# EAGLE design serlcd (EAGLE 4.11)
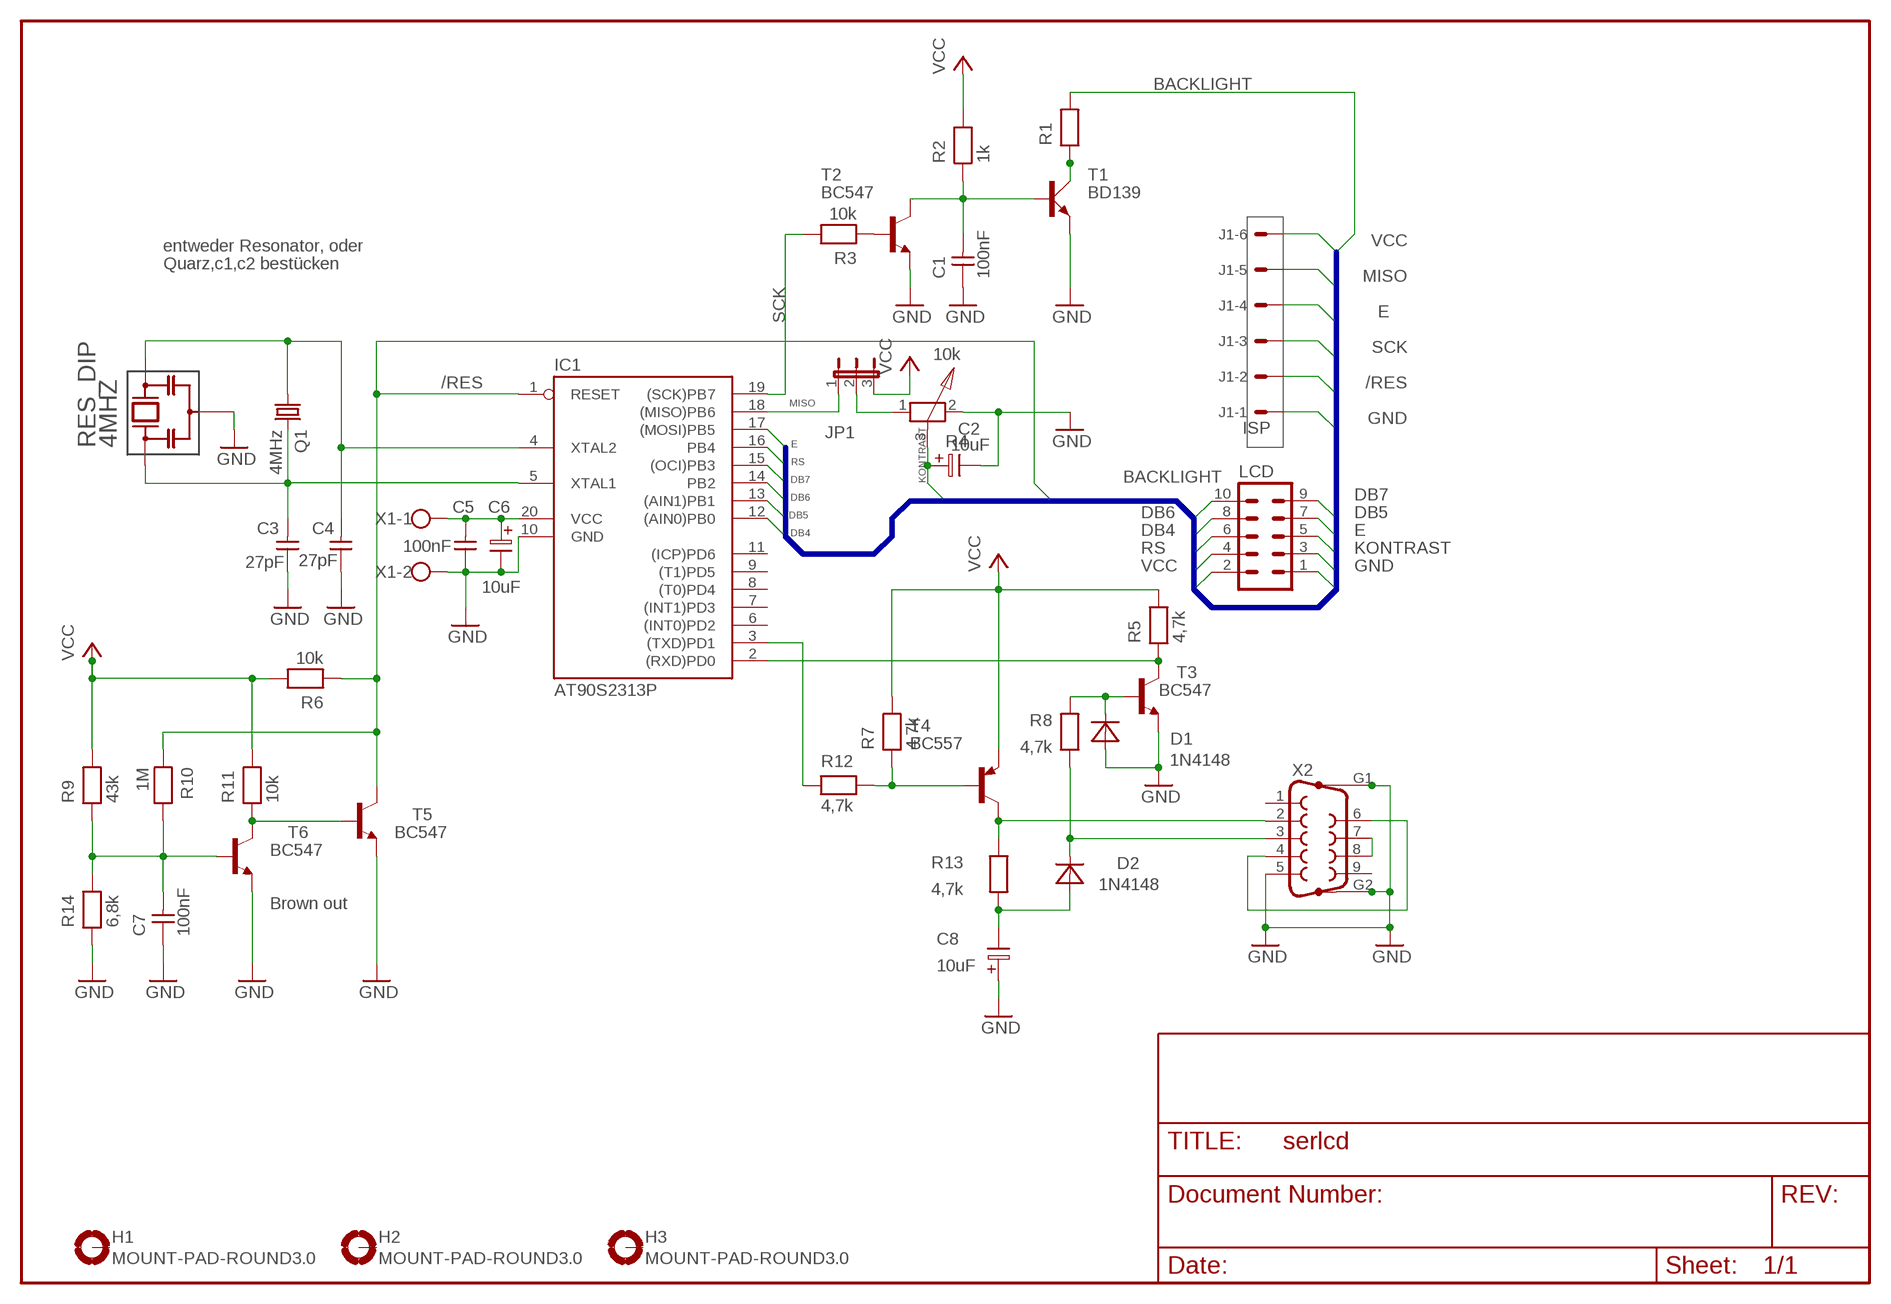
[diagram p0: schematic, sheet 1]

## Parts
4MHZ  RES_DIP  [RESONDIP]
C1  100nF  CAPNP-5  [C-5]
C2  10uF  ELC-2,5  [ES-2,5]
C3  27pF  CAPNP-2,5  [C-2,5]
C4  27pF  CAPNP-2,5  [C-2,5]
C5  100nF  CAPNP-5  [C-5]
C6  10uF  ELC-2,5  [ES-2,5]
C7  100nF  CAPNP-5  [C-5]
C8  10uF  ELC-2,5  [ES-2,5]
D1  1N4148  DIODE-7,5  [D-7,5]
D2  1N4148  DIODE-7,5  [D-7,5]
H1  MOUNT-PAD-ROUND3.0  [3,0-PAD]
H2  MOUNT-PAD-ROUND3.0  [3,0-PAD]
H3  MOUNT-PAD-ROUND3.0  [3,0-PAD]
IC1  AT90S2313P  [DIL20]
J1  ISP  22-27-2061-06  [6410-06]
JP1  JP2E  [JP2]
LCD  ML10  [ML10]
Q1  4MHz  CRYTALHC49S  [HC49/S]
R1  RESEU-12,5  [R-12,5]
R2  1k  RESEU-7,5  [R-7,5]
R3  10k  RESEU-7,5  [R-7,5]
R4  10k  POT-L  [PT-10]
R5  4,7k  RESEU-7,5  [R-7,5]
R6  10k  RESEU-7,5  [R-7,5]
R7  4,7k  RESEU-7,5  [R-7,5]
R8  4,7k  RESEU-7,5  [R-7,5]
R9  43k  RESEU-7,5  [R-7,5]
R10  1M  RESEU-7,5  [R-7,5]
R11  10k  RESEU-7,5  [R-7,5]
R12  4,7k  RESEU-7,5  [R-7,5]
R13  4,7k  RESEU-7,5  [R-7,5]
R14  6,8k  RESEU-7,5  [R-7,5]
T1  BD139  [TO126AV]
T2  BC547  [TO92]
T3  BC547  [TO92]
T4  BC557  [TO92]
T5  BC547  [TO92]
T6  BC547  [TO92]
X1  W237-102  [W237-102]
X2  F09HP  [F09HP]

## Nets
/RES: IC1.1(RESET) J1.2 R6.1 R10.1 T5.3(C)
BACKLIGHT: LCD.10 R1.2
DB4: IC1.12((AIN0)PB0) LCD.6
DB5: IC1.13((AIN1)PB1) LCD.7
DB6: IC1.14(PB2) LCD.8
DB7: IC1.15((OCI)PB3) LCD.9
E: IC1.17((MOSI)PB5) J1.4 LCD.5
GND: 4MHZ.GND C1.1 C2.2 C3.1 C4.1 C5.1 C6.2 C7.1 C8.1 D1.1(A) IC1.10(GND) J1.1 LCD.1 R4.2 R14.1 T1.E T2.1(E) T3.1(E) T5.1(E) T6.1(E) X1.2 X2.5 X2.G1 X2.G2
KONTRAST: C2.1 LCD.3 R4.3
MISO: IC1.18((MISO)PB6) J1.5 JP1.1
N$1: 4MHZ.IN C3.2 IC1.5(XTAL1) Q1.2
N$2: IC1.3((TXD)PD1) R12.1
N$3: 4MHZ.OUT C4.2 IC1.4(XTAL2) Q1.1
N$4: R7.1 R12.2 T4.2(B)
N$5: R13.2 T4.3(C) X2.2
N$6: D2.2(K) R8.1 X2.3
N$7: C8.2 D2.1(A) R13.1
N$8: D1.2(K) R8.2 T3.2(B)
N$9: IC1.2((RXD)PD0) R5.1 T3.3(C)
N$12: C7.2 R9.1 R10.2 R14.2 T6.2(B)
N$13: R11.1 T5.2(B) T6.3(C)
N$15: C1.2 R2.1 T1.B T2.3(C)
N$18: R3.1 T2.2(B)
N$20: R1.1 T1.C
N$21: JP1.2 R4.1
N$24: X2.7 X2.8
N$25: X2.4 X2.6
RS: IC1.16(PB4) LCD.4
SCK: IC1.19((SCK)PB7) J1.3 R3.2
VCC: C5.2 C6.1 IC1.20(VCC) J1.6 JP1.3 LCD.2 R2.2 R5.2 R6.2 R7.2 R9.2 R11.2 T4.1(E) X1.1
Unconnected: H1.B3,0(MOUNT) H2.B3,0(MOUNT) H3.B3,0(MOUNT) IC1.6((INT0)PD2) IC1.7((INT1)PD3) IC1.8((T0)PD4) IC1.9((T1)PD5) IC1.11((ICP)PD6) X2.1 X2.9

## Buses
DB[4..7],KONTRAST,BACKLIGHT,VCC,GND,E,RS,/RES,SCK,MISO

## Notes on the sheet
- entweder Resonator, oder
- Quarz,c1,c2 bestücken
- Brown out

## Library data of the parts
4MHZ = 0_jmw:RES_DIP
C1 C5 C7 = discrete:CAPNP-5
C2 C6 C8 = discrete:ELC-2,5
C3 C4 = discrete:CAPNP-2,5
D1 D2 = discrete:DIODE-7,5
H1-H3 = holes:MOUNT-PAD-ROUND: MOUNTING PAD, round
IC1 = atmel:AT90S2313: MICROCONTROLLER 2 Kbytes FLASH 128 bytes SRAM 128 bytes EEPROM UART
J1 = ep_molex_6410_7395-02:22-?-06: CONNECTOR wire to board 2.54 mm (.1 inch) pitch header
JP1 = jumper:JP2E: JUMPER
LCD = con-ml:ML10: HARTING
Q1 = crystal:CRYTAL: CRYSTAL
R1 = discrete:RESEU-12,5
R2 R3 R5-R14 = discrete:RESEU-7,5
R4 = discrete:POT-L
T1 = transistor-power:BD139: NPN TRANSISTOR
T2 T3 T5 T6 = transistor:BC547: NPN TRANSISTOR
T4 = transistor-pnp:BC557: PNP Transistor
X1 = con-wago-500:W237-102: WAGO SCREW CLAMP
X2 = con-subd:F09HP: SUB-D

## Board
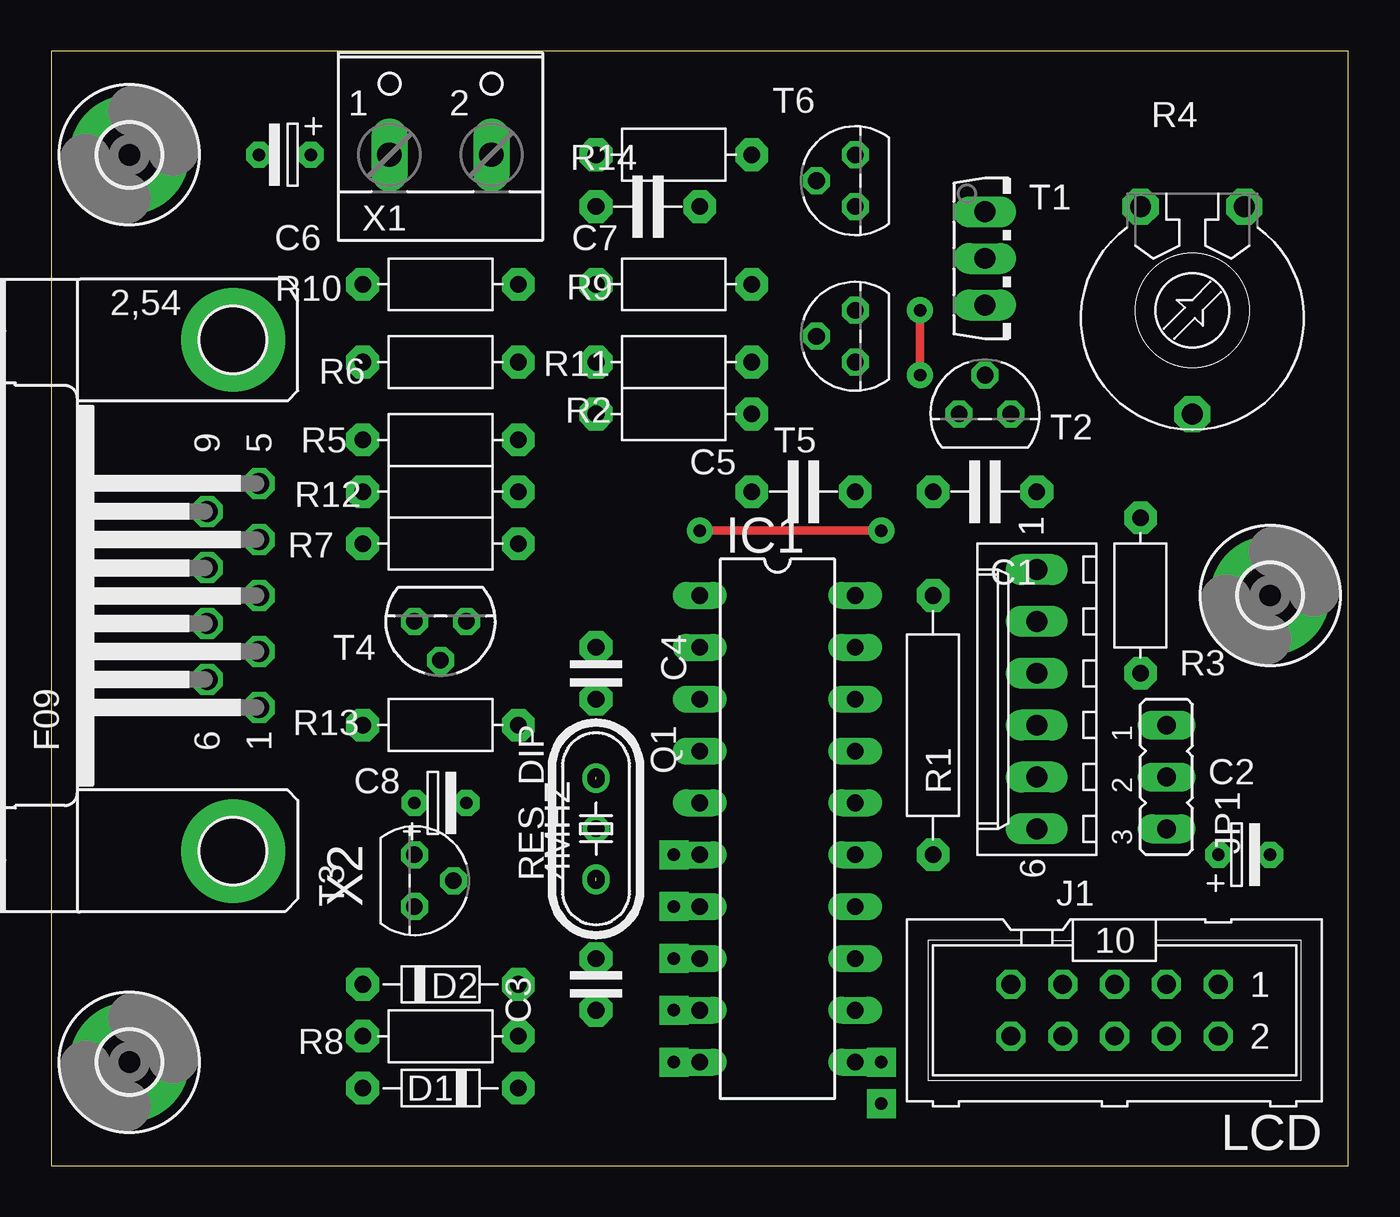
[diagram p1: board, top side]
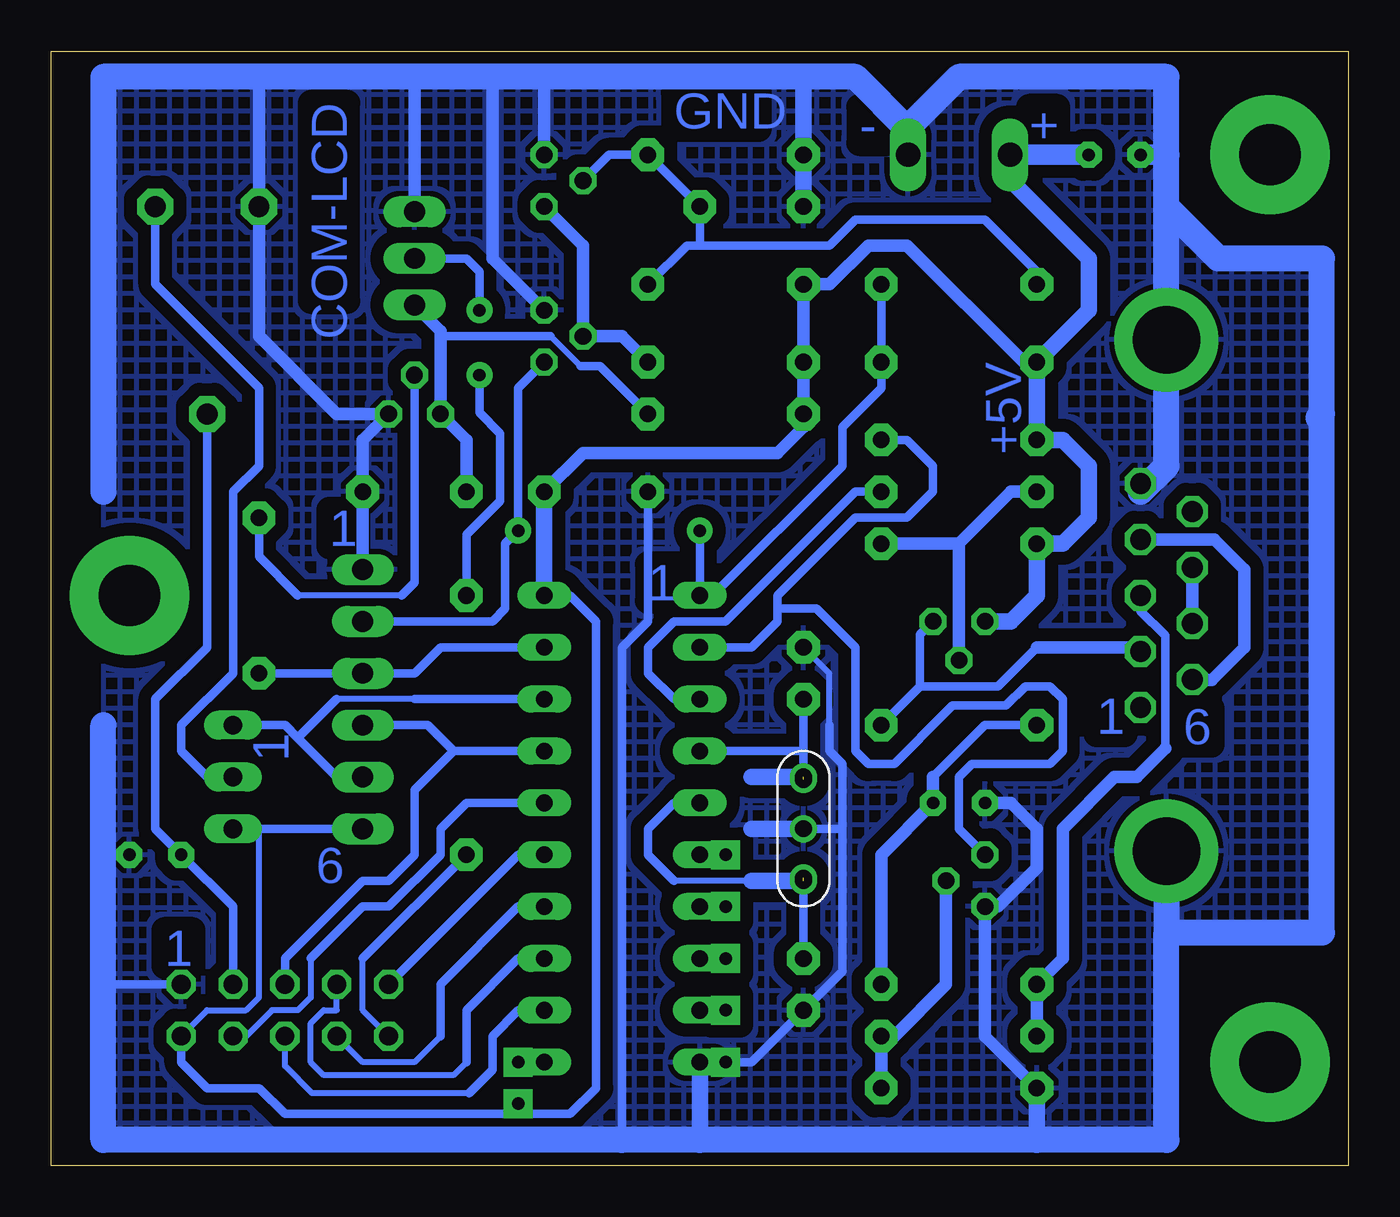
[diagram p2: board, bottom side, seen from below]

Size 63.55 x 54.6 mm. Coordinates in mm from the lower left corner, seen from the top.
Outline: 0,0 63.55,0 63.55,54.6 0,54.6 0,0
Copper layers (1*16): Top 0.035mm / dielectric 1.5mm / Bottom 0.035mm
Design rules "default": minimum track width 10mil, minimum drill 24mil, track to track 25mil, track to pad 25mil, pad to pad 25mil, via to via 25mil, smd to smd 8mil, copper to edge 40mil, drill to drill 8mil, minimum pad ring 10mil, minimum via ring 8mil, stop-mask expansion 4mil, vias tented up to drill 0mil, thermal gap 10mil

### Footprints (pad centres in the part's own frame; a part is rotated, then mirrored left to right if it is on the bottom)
RESONDIP = drill 0.813 round: GND 0,0; IN -2.54,0; OUT 2.54,0
C-5 = drill 0.813 pad 1.6 octagon: 1 -2.54,0; 2 2.54,0
ES-2,5 = drill 0.61 pad 1.27 octagon: 1 -1.27,0; 2 1.27,0
C-2,5 = drill 0.813 pad 1.6 octagon: 1 -1.27,0; 2 1.27,0
D-7,5 = drill 0.813 pad 1.6 octagon: 1 -3.81,0; 2 3.81,0
3,0-PAD = drill 3 pad 5.842 round: B3,0 0,0
DIL20 = drill 0.813 long: 1 -11.43,-3.81; 2 -8.89,-3.81; 3 -6.35,-3.81; 4 -3.81,-3.81; 5 -1.27,-3.81; 6 1.27,-3.81; 7 3.81,-3.81; 8 6.35,-3.81; 9 8.89,-3.81; 10 11.43,-3.81; 11 11.43,3.81; 12 8.89,3.81; 13 6.35,3.81; 14 3.81,3.81; 15 1.27,3.81; 16 -1.27,3.81; 17 -3.81,3.81; 18 -6.35,3.81; 19 -8.89,3.81; 20 -11.43,3.81
6410-06 = drill 1.016 long: 1 6.35,0; 2 3.81,0; 3 1.27,0; 4 -1.27,0; 5 -3.81,0; 6 -6.35,0
JP2 = drill 0.914 long: 1 -2.54,0; 2 0,0; 3 2.54,0
ML10 = drill 0.914 octagon: 1 -5.08,-1.27; 2 -5.08,1.27; 3 -2.54,-1.27; 4 -2.54,1.27; 5 0,-1.27; 6 0,1.27; 7 2.54,-1.27; 8 2.54,1.27; 9 5.08,-1.27; 10 5.08,1.27
HC49/S = drill 0.813 round: 1 -2.413,0; 2 2.413,0
R-12,5 = drill 0.813 pad 1.6 octagon: 1 -6.35,0; 2 6.35,0
R-7,5 = drill 0.813 pad 1.6 octagon: 1 -3.81,0; 2 3.81,0
PT-10 = drill 1.016 pad 1.778 octagon: 1 -2.54,-5.08; 2 2.54,-5.08; 3 0,5.08
TO126AV = drill 1.016 long: B 2.286,-1.27; C 0,-1.27; E -2.286,-1.27
TO92 = drill 0.813 octagon: 1 1.27,0; 2 0,1.905; 3 -1.27,0
HEBW21 = drill 2.184 pad 2.54 long: MASSE 0,6.5; STIFT 0,0.3; ÖFFNER -5.3,3.4
W237-102 = drill 1.194 long: 1 -2.5,-1.27; 2 2.5,-1.27
F09HP = drill 1.016 octagon: 1 -5.486,-1.27; 2 -2.743,-1.27; 3 0,-1.27; 4 2.743,-1.27; 5 5.486,-1.27; 6 -4.115,1.27; 7 -1.372,1.27; 8 1.372,1.27; 9 4.115,1.27 | drill 3.302 pad 5.08 round: G1 -12.522,0; G2 12.522,0

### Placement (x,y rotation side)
4MHZ  26.7,16.5 90 top
C1  45.75,33.02 180 top
C2  58.45,15.24 0 top
C3  26.7,8.88 90 top
C4  26.7,24.12 270 top
C5  36.86,33.02 0 top
C6  11.46,49.52 180 top
C7  29.24,46.98 0 top
C8  19.08,17.78 0 top
D1  19.08,3.8 0 top
D2  19.08,8.88 180 top
H1  3.84,49.52 0 top
H2  59.72,27.94 0 top
H3  3.84,5.08 0 top
IC1  35.59,16.5 270 top
J1  48.29,22.86 90 top
JP1  54.64,19.05 270 top
LCD  52.1,7.61 180 top
Q1  26.7,16.5 270 top
R1  43.21,21.59 270 top
R2  30.51,36.83 180 top
R3  53.37,27.94 270 top
R4  55.91,41.91 180 top
R5  19.08,35.55 180 top
R6  19.08,39.37 180 top
R7  19.08,30.48 180 top
R8  19.08,6.34 0 top
R9  30.51,43.17 180 top
R10  19.08,43.17 180 top
R11  30.51,39.37 180 top
R12  19.08,33.02 180 top
R13  19.08,21.59 0 top
R14  30.51,49.52 0 top
T1  47.02,44.45 270 top
T2  45.75,36.83 0 top
T3  17.81,13.96 270 top
T4  19.08,26.66 180 top
T5  39.4,40.63 90 top
T6  39.4,48.26 90 top
U$1  POWERBUCHSE21  [HEBW21]  not placed on the board
X1  19.08,50.8 0 top
X2  8.92,27.94 90 top

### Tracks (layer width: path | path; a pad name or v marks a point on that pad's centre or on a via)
/RES  (via drill 0.61 pad 1.27)
  Top 0.406: v31.78,31.11 v40.67,31.11
  Bottom 0.406: R10.1 R6.1 22.89,38.09 24.79,36.19 24.79,34.29 31.14,27.94 IC1.1 v31.78,31.11 | T5.3 40.67,38.09 v40.67,31.11 41.3,30.48 41.3,27.3 41.94,26.66 J1.2
BACKLIGHT
  Bottom 0.305: LCD.10 48.29,7.61 48.29,10.16
  Bottom 0.406: 48.29,10.16 R1.2
DB4
  Bottom 0.305: LCD.6 52.1,4.88 50.76,3.55 43.08,3.55
  Bottom 0.406: IC1.12 40.67,7.61 41.94,6.34 41.94,4.69 43.08,3.55
DB5
  Bottom 0.305: LCD.7 49.56,7.61 50.19,7.61 50.83,6.98 50.83,5.08 50.19,4.44 43.84,4.44 43.21,5.08
  Bottom 0.406: IC1.13 40.67,10.16 43.21,7.61 43.21,5.08
DB6
  Bottom 0.305: 44.48,6.34 45.75,5.08 48.29,5.08 LCD.8
  Bottom 0.406: IC1.14 40.67,12.7 44.48,8.88 44.48,6.34
DB7
  Bottom 0.406: IC1.15 40.67,15.24 LCD.9
E
  Bottom 0.406: 43.84,20.32 45.75,18.41 45.75,15.24 47.02,13.96 48.29,13.96 52.1,10.16 LCD.5 | IC1.17 43.84,20.32 | J1.4 45.11,21.59 43.84,20.32
GND  (via drill 0.61 pad 1.42)
  Bottom 0.305: C4.1 25.43,24.12 25.43,21.59
  Bottom 0.406: IC1.10 v30.51,5.08 29.24,5.08 C3.1 24.79,9.52 24.79,16.5 | 60.99,8.88 LCD.1 | 24.79,16.5 24.79,19.68 25.43,20.32 25.43,21.59 | 24.79,16.5 4MHZ.GND | C5.1 34.32,26.66 35.59,25.39 35.59,1.26
  Bottom 0.61: D1.1 17.81,6.34 T3.1 17.17,12.7 15.27,14.6 15.27,16.5 16.54,17.78 C8.1 | 39.4,53.34 T6.1 | 45.75,53.34 T1.E | T5.1 41.94,44.45 41.94,53.34 | J1.1 C1.1 48.29,35.55 T2.1 49.56,36.83 53.37,40.63 R4.2 53.37,53.34
  Bottom 0.813: C7.1 R14.1 26.7,53.34 | 15.27,1.26 D1.1 | 31.78,1.26 IC1.10 | 4MHZ.GND 29.24,16.5
  Bottom 1.016: 8.92,49.52 C6.2
  Bottom 1.27: X1.2 21.58,50.76 24.16,53.34 26.7,53.34 39.4,53.34 41.94,53.34 45.75,53.34 53.37,53.34 60.99,53.34 60.99,33.02 | 1.3,36.83 1.47,36.65 | 1.3,36.83 1.3,44.45 6.38,44.45 8.92,46.98 | 8.92,46.98 8.92,49.52 8.92,53.34 19.08,53.34 21.62,50.8 21.62,49.52 | 8.92,11.43 1.3,11.43 1.3,36.83 | 8.92,11.43 8.92,1.26 15.27,1.26 31.78,1.26 35.59,1.26 60.99,1.26 60.99,8.88 60.99,21.59 | 10.19,33.02 8.92,34.29 8.92,46.98 | 8.92,15.24 8.92,11.43
  pour Bottom (isolate 0.254, hatched): 8.92,53.34 19.08,53.34 21.62,50.8 24.16,53.34 60.99,53.34 60.99,1.26 8.92,1.26 8.92,11.43 1.3,11.43 1.3,44.45 6.38,44.45 8.92,46.98
KONTRAST
  Bottom 0.406: LCD.3 54.64,12.7 C2.1 58.45,16.5 58.45,22.86 55.91,25.39 R4.3
MISO
  Bottom 0.305: 45.75,22.86 49.56,22.86
  Bottom 0.406: J1.5 49.56,19.05 51.46,20.95 | 51.46,20.95 52.1,21.59 JP1.1 | 49.56,22.86 51.46,20.95 | IC1.18 45.75,22.86
N$1  (1 unrouted)
  Bottom 0.305: 29.24,13.96 33.05,13.96
  Bottom 0.406: C3.2 4MHZ.IN | 33.05,13.96 34.32,15.24 34.32,16.5 33.05,17.78 IC1.5
  Bottom 0.813: 4MHZ.IN 29.24,13.96
N$2
  Bottom 0.406: R12.1 24.16,33.02 30.51,26.66 33.05,26.66 34.32,25.39 34.32,24.12 33.05,22.86 IC1.3
N$3  (1 unrouted)
  Bottom 0.406: 4MHZ.OUT 26.7,20.32 | 26.7,20.32 C4.2 | 26.7,20.32 IC1.4
  Bottom 0.813: 4MHZ.OUT 29.24,19.05
N$4
  Bottom 0.61: T4.2 19.08,30.48 | 19.08,30.48 R7.1 | R12.2 16.54,33.02 19.08,30.48
N$5
  Bottom 0.406: 20.98,23.49 R13.2 | T4.3 20.98,26.03 20.98,23.49 | 20.98,23.49 17.17,23.49 15.27,25.39 | X2.2 10.19,25.39
  Bottom 0.61: 10.19,25.39 15.27,25.39
N$6
  Bottom 0.406: X2.3 10.19,27.17 8.98,25.97 8.98,20.44
  Bottom 0.61: R8.1 D2.2 14,10.16 14,16.5 11.46,19.05 10.38,19.05 8.98,20.44
N$7
  Bottom 0.406: R13.1 17.81,21.59 20.35,19.05
  Bottom 0.61: 20.35,19.05 C8.2 22.89,15.24 D2.1
N$8
  Bottom 0.61: D1.2 R8.2 22.25,6.34 19.71,8.88 T3.2
N$9
  Bottom 0.406: T3.3 19.08,16.5 19.08,19.05 18.44,19.68 14.63,19.68 14,20.32 14,22.86 14.63,23.49 15.84,23.49 16.79,22.54 19.39,22.54 19.71,22.22 22.25,19.68 23.52,19.68 24.16,20.32 24.16,25.39 26.06,27.3 27.97,27.3 | R5.1 21.62,35.55 20.35,34.29 20.35,33.02 21.62,31.75 24.16,31.75 27.97,27.94 27.97,27.3 | 27.97,27.3 27.97,26.66 29.24,25.39 IC1.2
N$12
  Bottom 0.406: T6.2 36.22,49.52 R14.2 C7.2 31.78,45.08 | 31.78,45.08 25.43,45.08 24.16,46.35 17.81,46.35 15.27,43.81 R10.2 | 31.78,45.08 32.41,45.08 R9.1
N$13
  Bottom 0.61: R11.1 35.59,40.63 T5.2 37.49,45.08 T6.3
N$14  (via drill 0.61 pad 1.42)
  other vias: 30.51,7.61
N$15
  Bottom 0.305: 37.62,39.17 39.08,40.63
  Bottom 0.406: 39.08,40.63 44.48,40.63 | 37.62,39.17 36.66,39.17 R2.1
  Bottom 0.61: C1.2 43.21,35.55 T2.3 44.48,40.63 44.48,40.89 T1.B
N$16  (via drill 0.61 pad 1.42)
  other vias: 30.51,10.16
N$17  (via drill 0.61 pad 1.42)
  other vias: 30.51,12.7
N$18
  Bottom 0.305: 46.38,27.94 51.46,27.94
  Bottom 0.406: T2.2 45.75,28.57 46.38,27.94 | 51.46,27.94 53.37,29.84 R3.1
N$19  (via drill 0.61 pad 1.42)
  other vias: 30.51,15.24
N$20  (via drill 0.61 pad 1.27)
  Top 0.406: v42.57,38.73 v42.57,41.91
  Bottom 0.406: T1.C 43.21,44.45 42.57,43.81 v42.57,41.91 | R1.1 43.21,30.92 41.55,32.57 41.55,35.87 42.57,36.89 v42.57,38.73
N$21
  Bottom 0.406: JP1.2 55.91,19.05 57.18,20.32 57.18,21.59 54.64,24.12 54.64,33.02 53.37,34.29 53.37,38.09 58.45,43.17 R4.1
N$22  (via drill 0.61 pad 1.42)
  other vias: 40.67,3.04
N$23  (via drill 0.61 pad 1.42)
  other vias: 40.67,5.08
N$24
  Bottom 0.61: X2.7 X2.8
N$25
  Bottom 0.406: 7.65,23.81 X2.6
  Bottom 0.61: X2.4 6.58,30.68 5.11,29.21 5.11,25.39 6.69,23.81 7.65,23.81
RS
  Bottom 0.305: 50.83,10.16 50.83,8.25 51.46,7.61 52.73,7.61 54,6.34 LCD.4
  Bottom 0.406: IC1.16 43.21,17.78 44.48,16.5 44.48,15.24 47.02,12.7 48.29,12.7 50.83,10.16
SCK
  Bottom 0.406: R3.2 J1.3 45.75,24.12 44.48,25.39 IC1.19
VCC
  Bottom 0.305: LCD.2 55.91,7.61 54,7.61 53.37,8.25 53.37,16.5
  Bottom 0.406: J1.6 53.37,16.5 JP1.3 | IC1.20 38.13,27.94 36.86,26.66 36.86,3.8 38.13,2.54 52.1,2.54 53.37,3.8 55.91,3.8 57.18,5.08 LCD.2
  Bottom 0.61: R6.2 15.9,39.37 21.62,45.08 23.52,45.08 25.43,43.17 R9.2 R11.2 R2.2 26.7,36.19 27.97,34.92 37.49,34.92 C5.2
  Bottom 0.813: X1.1 16.58,48.3 12.73,44.45 12.73,41.91 R6.2 R5.2 14,35.55 12.73,34.29 12.73,31.75 14,30.48 R7.2 15.27,27.94 16.54,26.66 T4.1 | IC1.20 C5.2
  Bottom 1.016: X1.1 C6.1

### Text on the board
Bottom: COM-LCD | GND | + | - | +5V | 1 | 1 | 1 | 6 | 1 | 6 | 1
